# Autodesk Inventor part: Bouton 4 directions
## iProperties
Created: 2010-07
Part Number: Bouton 4 directions
Document SubType Name: Modeling
Designer: eric
Density: 1 g/cm^3
Author: eric
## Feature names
1. Base1
